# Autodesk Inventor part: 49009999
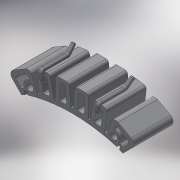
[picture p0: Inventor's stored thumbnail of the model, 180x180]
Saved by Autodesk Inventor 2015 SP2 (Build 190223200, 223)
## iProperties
Created: 2017-06
Part Number: 49009999
Material: Generic
Description: PLASSON FLEX RESTRAINT
Document SubType Name: Modeling
Designer: KIM
Density: 1 g/cm^3
Appearance: Default
Author: KIM
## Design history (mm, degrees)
derived "49009.ipt"
feature "Solid1::49009.ipt"
tag "TaggingFeature1"
body "Solid1"
other parameters: "d54" = 202, "d95" = 256, "d102" = 8.5, "d161" = 65, "d162" = 0, "d163" = 2, "d216" = 45 deg, "d223" = 2, "d224" = 6, "d225" = 6, "d226" = 6, "d227" = 6, "d228" = 0.5, "d229" = 0.5, "d230" = 0.5, "d231" = 135 deg, "d233" = 45, "d234" = 35, "d235" = 6, "d236" = 0, "d237" = 6, "d238" = 1, "d239" = 2, "d240" = 2, "L_" = 202, "B_" = 65
